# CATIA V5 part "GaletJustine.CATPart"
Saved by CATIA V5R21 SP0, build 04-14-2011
Part number: GaletJustine
Bounding box of the stored display mesh (mm): x 0 to 11, y -8.955 to 31.045, z -16.273 to 49.927
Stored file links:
  C:\Users\2027.DESARCY-LEMIE30\Desktop\V16(05.04.2023)\GaletJustine.CATPart
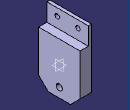
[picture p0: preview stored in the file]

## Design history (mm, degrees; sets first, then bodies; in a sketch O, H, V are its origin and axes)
Body1 (main body)
  Sketch1 on yz-plane, origin (0, 0, 0), H (0, 1, 0), V (0, 0, 1)
    line L1 (0.2374, -16.2729) -> (21.8526, -16.2729)
    line L2 (21.8526, -16.2729) -> (31.045, -7.0805)
    point P3 (31.045, -7.0805)
    line L3 (0.2374, -16.2729) -> (-8.955, -7.0805)
    line L4 (-8.955, -7.0805) -> (-8.955, 49.9271)
    line L5 (31.045, -7.0805) -> (31.045, 49.9271)
    point P6 (31.045, -7.0805)
    line L6 (-8.955, 49.9271) -> (31.045, 49.9271)
    circle A1 centre (11.045, -7.2729) radius 3
    point P8 (11.045, -7.2729)
    length L3 = 13
    angle L1 L3 = 45
    length L2 = 13
    distance L1 L6 = 66.2
    length L6 = 40
    radius A1 = 3
    distance P8 L5 = 20
    distance P8 L1 = 9
    horizontal: L1 H, L6 H
    perpendicularity: L3 L2
    vertical: L4 V, L5 V
    coincidence: P6 L2, P3 P6
  Pad1: profile Sketch1, direction (1, 0, 0), length 11
  Sketch2 on end face of Pad1, origin (11, 0, 0), H (0, 1, 0), V (0, 0, 1)
    line L1 (-8.955, 49.9271) -> (31.045, 49.9271)
    line L2 (31.045, 49.9271) -> (31.045, 32.9271)
    line L3 (-8.955, 49.9271) -> (-8.955, 32.9271)
    line L4 (-8.955, 32.9271) -> (31.045, 32.9271)
    reference projected line E1 (31.045, 49.9271) -> (-8.955, 49.9271) from edge [face of Pad1 from Sketch1.L6 | end face of Pad1]
    reference projected line E2 (31.045, -7.0805) -> (31.045, 49.9271) from edge [face of Pad1 from Sketch1.L5 | end face of Pad1]
    reference projected line E3 (-8.955, 49.9271) -> (-8.955, -7.0805) from edge [face of Pad1 from Sketch1.L4 | end face of Pad1]
    length L3 = 17
    horizontal: L1 H, L4 H
    vertical: L2 V, L3 V
    coincidence: L1 E1, L2 E2, L3 E3
  Pocket1: profile Sketch2, direction (-1, 0, 0), length 8
  Sketch3 on end face of Pocket1, origin (3, 0, 0), H (0, 1, 0), V (0, 0, 1)
    circle A1 centre (1.045, 42.9271) radius 2.25
    point P1 (1.045, 42.9271)
    circle A2 centre (21.045, 42.9271) radius 2.25
    point P2 (21.045, 42.9271)
    reference projected line E1 (-8.955, 49.9271) -> (-8.955, 32.9271) from edge [face of Pad1 from Sketch1.L4 | end face of Pocket1]
    reference projected line E2 (-8.955, 32.9271) -> (31.045, 32.9271) from edge [end face of Pad1 | face of Pocket1 from Sketch2.L4]
    reference projected line E3 (-8.955, 32.9271) -> (31.045, 32.9271) from edge [end face of Pad1 | face of Pocket1 from Sketch2.L4]
    reference projected line E4 (31.045, 32.9271) -> (31.045, 49.9271) from edge [face of Pad1 from Sketch1.L5 | end face of Pocket1]
    radius A1 = 2.25
    radius A2 = 2.25
    distance P1 E1 = 10
    distance P1 E2 = 10
    distance P2 E3 = 10
    distance P2 E4 = 10
  Pocket2: profile Sketch3, direction (-1, 0, 0), length 3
